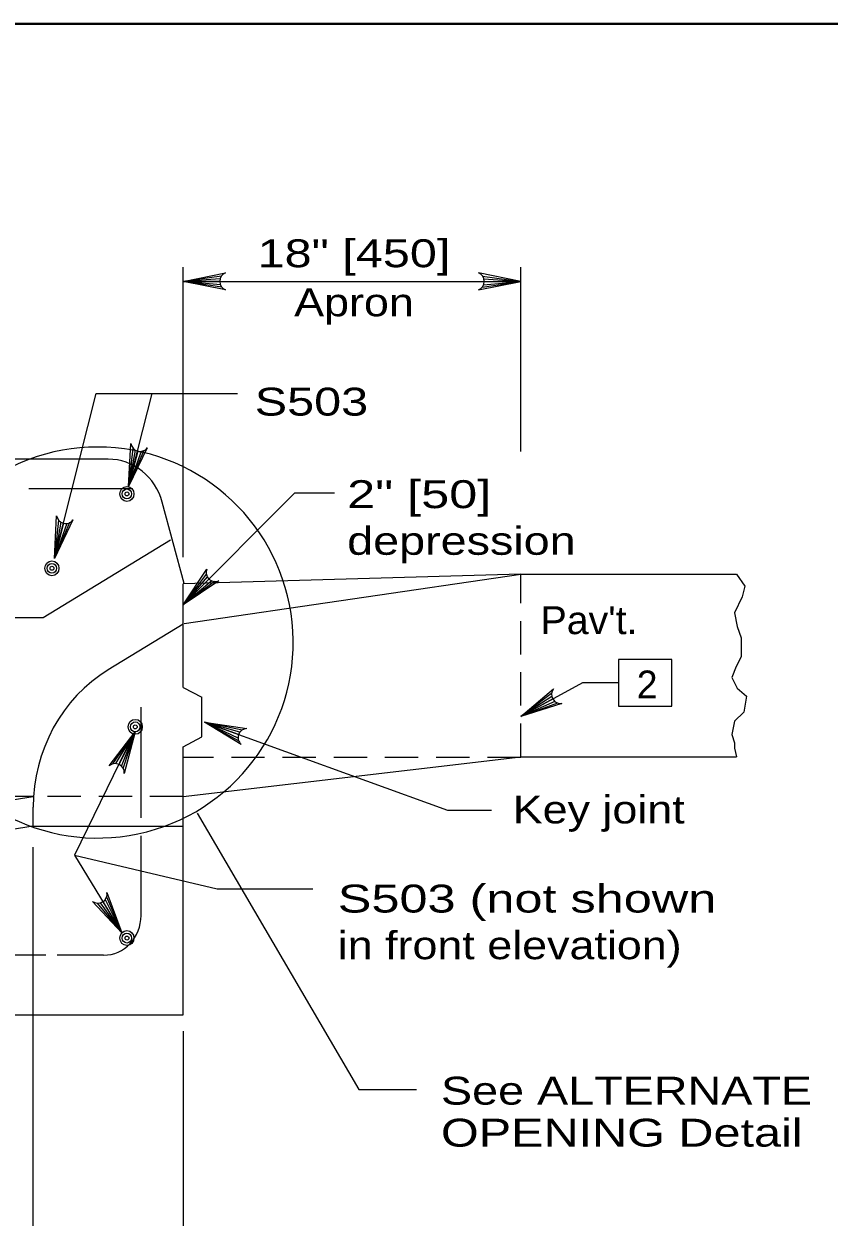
# Model space of a CAD drawing. Extents: x 339.1 to 373.1, y 1412.7 to 1456.7.
# Drawn here: x 360.75 to 365.24, y 1427.58 to 1434.25 of the extents above; entities that cross this region are included whole.
import ezdxf
from ezdxf.enums import TextEntityAlignment as Align

# ---------------------------------------------------------------- set-up
doc = ezdxf.new("R2010")
doc.units = 0
doc.header["$LTSCALE"] = 0.062
doc.linetypes.add('MEDIUM_DASHED', pattern=[4.5, 3, -1.5])
doc.layers.add('1', color=7, linetype='Continuous', lineweight=13)

msp = doc.modelspace()

# ---------------------------------------------------------------- linework, layer by layer
at = {"layer": '1', "lineweight": 25}
for p, q in [((341.0605, 1434.2455), (372.5605, 1434.2455)), ((361.21592, 1431.81325), (358.1795, 1431.81325)), ((361.64092, 1431.11775), (361.51792, 1431.57225)), ((361.56425, 1431.36117), (360.85292, 1430.92642)), ((363.51942, 1431.17025), (361.63475, 1431.1175)), ((361.64092, 1430.896), (363.51942, 1431.17025)), ((363.51942, 1431.17025), (364.7245, 1431.17025)), ((361.63475, 1430.53842), (361.63475, 1431.1175)), ((360.85292, 1430.92642), (358.703, 1430.92642)), ((361.63475, 1430.89225), (361.21592, 1430.63617)), ((361.63475, 1430.53842), (361.73942, 1430.483)), ((361.73942, 1430.26125), (361.73942, 1430.483)), ((361.63475, 1430.20583), (361.73942, 1430.26125)), ((361.63475, 1428.70933), (361.63475, 1430.20583)), ((361.63475, 1429.92875), (363.51942, 1430.15042)), ((363.51942, 1430.15042), (364.72342, 1430.15042)), ((360.79708, 1429.76242), (360.79708, 1429.86817)), ((360.79708, 1429.76242), (359.75008, 1429.59617)), ((360.79708, 1429.76242), (361.63483, 1429.76242)), ((357.86533, 1428.70933), (361.63475, 1428.70933))]:
    msp.add_line(p, q, dxfattribs=at)
at = {"layer": '1'}
for p, q in [((361.63475, 1431.26658), (361.63475, 1432.88542)), ((363.51942, 1431.85642), (363.51942, 1432.88542)), ((361.848, 1432.83667), (361.63475, 1432.80675)), ((361.84083, 1432.82183), (361.63475, 1432.80675)), ((361.63475, 1432.80675), (363.011, 1432.80675)), ((361.83858, 1432.80675), (361.63475, 1432.80675)), ((361.84242, 1432.78767), (361.63475, 1432.80675)), ((361.85058, 1432.77383), (361.63475, 1432.80675)), ((363.011, 1432.80675), (363.51942, 1432.80675)), ((363.30367, 1432.77383), (363.51942, 1432.80675)), ((363.30617, 1432.83667), (363.51942, 1432.80675)), ((363.31183, 1432.78767), (363.51942, 1432.80675)), ((363.31342, 1432.82183), (363.51942, 1432.80675)), ((363.31558, 1432.80675), (363.51942, 1432.80675)), ((360.9155, 1431.25758), (361.14883, 1432.17967)), ((361.14883, 1432.17967), (361.9385, 1432.17967)), ((361.3285, 1431.66117), (361.46125, 1432.17967)), ((361.354, 1431.875), (361.3285, 1431.66117)), ((361.36642, 1431.86433), (361.3285, 1431.66117)), ((361.41542, 1431.8615), (361.3285, 1431.66117)), ((361.3805, 1431.85833), (361.3285, 1431.66117)), ((361.39992, 1431.85708), (361.3285, 1431.66117)), ((361.34683, 1431.64692), (360.77267, 1431.64692)), ((361.63475, 1430.99875), (362.2585, 1431.6245)), ((362.2585, 1431.6245), (362.47867, 1431.6245)), ((360.93892, 1431.47167), (360.9155, 1431.25758)), ((360.95142, 1431.46108), (360.9155, 1431.25758)), ((361.00042, 1431.45875), (360.9155, 1431.25758)), ((360.9655, 1431.45525), (360.9155, 1431.25758)), ((360.985, 1431.45417), (360.9155, 1431.25758)), ((361.76358, 1431.17133), (361.63475, 1430.99875)), ((361.769, 1431.15583), (361.63475, 1430.99875)), ((361.77817, 1431.14367), (361.63475, 1430.99875)), ((361.7945, 1431.13283), (361.63475, 1430.99875)), ((361.81, 1431.12892), (361.63475, 1430.99875)), ((363.69175, 1430.50442), (363.51942, 1430.37517)), ((363.6925, 1430.488), (363.51942, 1430.37517)), ((363.69792, 1430.47375), (363.51942, 1430.37517)), ((363.7105, 1430.45875), (363.51942, 1430.37517)), ((361.39917, 1429.80925), (361.39917, 1430.42758)), ((363.72433, 1430.45058), (363.51942, 1430.37517)), ((361.94417, 1430.2745), (361.75275, 1430.34467)), ((361.94108, 1430.25525), (361.75275, 1430.34467)), ((361.944, 1430.23942), (361.75275, 1430.34467)), ((361.95142, 1430.28792), (361.75275, 1430.34467)), ((361.96325, 1430.29925), (361.75275, 1430.34467)), ((361.24217, 1430.111), (361.36708, 1430.29)), ((361.25817, 1430.11225), (361.36708, 1430.29)), ((361.277, 1430.10708), (361.36708, 1430.29)), ((361.28958, 1430.0985), (361.36708, 1430.29)), ((361.29958, 1430.0855), (361.36708, 1430.29)), ((361.71317, 1429.83558), (362.61517, 1428.29108)), ((361.39917, 1429.26358), (361.39917, 1429.70858)), ((360.79708, 1427.18717), (360.79708, 1429.64608)), ((361.02717, 1429.60017), (361.82342, 1429.413)), ((361.82342, 1429.413), (362.35783, 1429.413)), ((361.15492, 1429.33267), (361.29125, 1429.16592)), ((361.17125, 1429.33417), (361.29125, 1429.16592)), ((361.18525, 1429.34008), (361.29125, 1429.16592)), ((361.19967, 1429.35333), (361.29125, 1429.16592)), ((361.20725, 1429.3675), (361.29125, 1429.16592)), ((360.86767, 1429.04192), (360.337, 1429.04192)), ((361.18975, 1429.04192), (360.931, 1429.04192)), ((361.63475, 1428.61708), (361.63475, 1426.47592)), ((362.61517, 1428.29108), (362.938, 1428.29108))]:
    msp.add_line(p, q, dxfattribs=at)
at = {"layer": '1', "linetype": 'MEDIUM_DASHED', "lineweight": 25}
for p, q in [((363.51942, 1430.15042), (363.51942, 1431.17025)), ((363.51942, 1430.14625), (361.63433, 1430.14625)), ((361.63475, 1429.92875), (360.79708, 1429.92875))]:
    msp.add_line(p, q, dxfattribs=at)
at = {"layer": '1', "lineweight": 40}
msp.add_lwpolyline([(341.0605, 1434.2455), (372.5605, 1434.2455), (372.5605, 1413.2455), (341.0605, 1413.2455)], close=True, dxfattribs=at)
at = {"layer": '1'}
for points in [[(361.87033, 1432.75967), (361.63475, 1432.80675), (361.87033, 1432.85392)], [(363.28383, 1432.75967), (363.51942, 1432.80675), (363.28383, 1432.85392)], [(361.43408, 1431.877), (361.3285, 1431.66117), (361.343, 1431.901)], [(361.019, 1431.47442), (360.9155, 1431.25758), (360.92767, 1431.49758)], [(361.834, 1431.133), (361.63475, 1430.99875), (361.76708, 1431.19933)], [(364.06525, 1430.56358), (363.86417, 1430.56358), (363.51942, 1430.37517)], [(363.74842, 1430.44783), (363.51942, 1430.37517), (363.70292, 1430.53033)], [(361.95775, 1430.21933), (361.75275, 1430.34467), (361.99017, 1430.30783)], [(361.75275, 1430.34467), (363.11042, 1429.85283), (363.35683, 1429.85283)], [(361.3515, 1430.26567), (361.02717, 1429.60017), (361.29125, 1429.16592)], [(361.22067, 1430.0995), (361.36708, 1430.29), (361.30525, 1430.05783)], [(361.20908, 1429.39175), (361.29125, 1429.16592), (361.1285, 1429.34275)]]:
    msp.add_lwpolyline(points, dxfattribs=at)
at = {"layer": '1', "lineweight": 25}
msp.add_lwpolyline([(364.7245, 1431.17025), (364.76983, 1431.10442), (364.75567, 1431.04433), (364.71317, 1430.95433), (364.72733, 1430.87925), (364.751, 1430.81433), (364.751, 1430.70925), (364.72258, 1430.65425), (364.69892, 1430.59417), (364.72733, 1430.53417), (364.77933, 1430.48917), (364.76508, 1430.39908), (364.71317, 1430.34908), (364.69892, 1430.274), (364.71317, 1430.229), (364.71317, 1430.199), (364.72342, 1430.15042)], dxfattribs=at)
for points in [[(364.06525, 1430.69442), (364.06525, 1430.43267), (364.36383, 1430.43267), (364.36383, 1430.69442)], [(360.79708, 1429.92875), (358.703, 1429.92875), (359.75008, 1429.76242)]]:
    msp.add_lwpolyline(points, close=True, dxfattribs=at)
at = {"layer": '1'}
for centre, radius, start, end in [((361.88936, 1432.80684), 0.05085, 112.08782, 247.91395), ((363.26483, 1432.80684), 0.05085, 292.08605, 67.91218), ((361.15655, 1430.78871), 1.09229, 203.13318, 168.75407), ((361.39335, 1431.90741), 0.05085, 187.32423, 323.15036), ((360.97793, 1431.50446), 0.05085, 187.89003, 323.71616), ((361.81387, 1431.17972), 0.05085, 157.36533, 293.19146), ((363.7423, 1430.4983), 0.05085, 140.99694, 276.82307), ((361.99184, 1430.2571), 0.05085, 91.96794, 227.79407), ((361.25461, 1430.06158), 0.05085, 355.85209, 131.67822), ((361.15886, 1429.38345), 0.05085, 233.39402, 9.22015)]:
    msp.add_arc(centre, radius, start, end, dxfattribs=at)
at = {"layer": '1', "lineweight": 25}
for centre, major_axis, start_param, end_param in [((361.21592, 1431.48066), (0, 0.33256), 4.9914937, 6.2831853), ((361.63474, 1429.86815), (0, 0.88682), 0.5235416, 1.5707963)]:
    msp.add_ellipse(centre, major_axis=major_axis, ratio=0.944544, start_param=start_param, end_param=end_param, dxfattribs=at)
at = {"layer": '1'}
for centre, major_axis in [((361.32063, 1431.61922), (0, 0.04157)), ((361.32063, 1431.61922), (0, -0.02771)), ((361.32063, 1431.61922), (0, 0.01109)), ((360.90181, 1431.20352), (0, 0.04157)), ((360.90181, 1431.20352), (0, -0.02771)), ((360.90181, 1431.20352), (0, 0.01109)), ((361.36712, 1430.3177), (0, 0.04157)), ((361.36712, 1430.3177), (0, 0.02771)), ((361.36712, 1430.3177), (0, 0.01109)), ((361.32063, 1429.13745), (0, 0.04157)), ((361.32063, 1429.13745), (0, 0.02771)), ((361.32063, 1429.13745), (0, 0.01109))]:
    msp.add_ellipse(centre, major_axis=major_axis, ratio=0.944544, dxfattribs=at)
msp.add_ellipse((361.18975, 1429.2636), major_axis=(0, -0.22171), ratio=0.944544, start_param=0, end_param=1.5707963, dxfattribs=at)

# ---------------------------------------------------------------- texts
for s, width, p in [('18" [450]', 1.3, (362.58825, 1432.88567)), ('Apron', 1.2, (362.58837, 1432.61167))]:
    msp.add_text(s, height=0.156, dxfattribs=dict(at, width=width)).set_placement(p, align=Align.CENTER)
for s, width, p in [('S503', 1.3, (362.03408, 1432.05667)), ('2" [50]', 1.35, (362.55033, 1431.53967)), ('depression', 1.25, (362.55033, 1431.279)), ("Pav't.", 1.05, (363.63033, 1430.83567)), ('Key joint', 1.2, (363.47492, 1429.778)), ('S503 (not shown', 1.35, (362.49775, 1429.28008)), ('in front elevation)', 1.2, (362.49775, 1429.01942)), ('See ALTERNATE', 1.25, (363.07392, 1428.20683)), ('OPENING Detail', 1.3, (363.07392, 1427.97217))]:
    msp.add_text(s, height=0.156, dxfattribs=dict(at, width=width)).set_placement(p)
msp.add_text('2', height=0.156, dxfattribs=at).set_placement((364.16717, 1430.47625))

doc.saveas('drawing.dxf')
